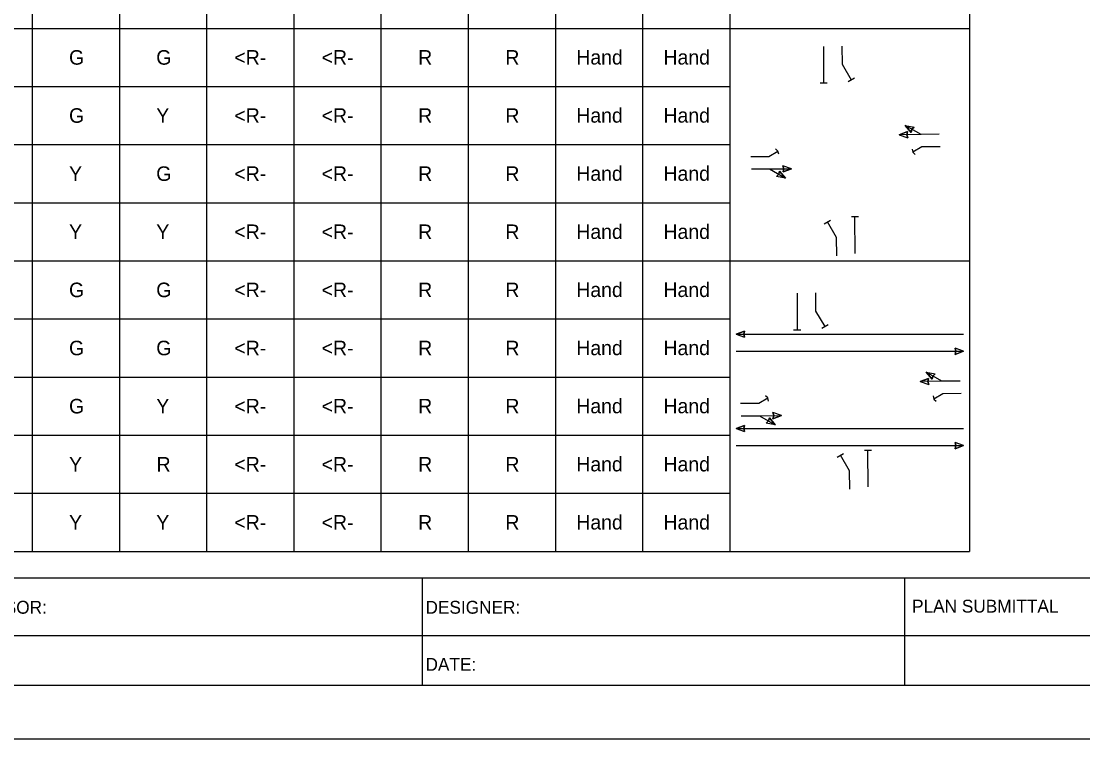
# Model space of a CAD drawing. Extents: x 515543 to 517243, y 660510 to 662861.
# Drawn here: x 515943.9 to 516438.4, y 660510.2 to 660844.6 of the extents above; entities that cross this region are included whole.
import ezdxf

# ---------------------------------------------------------------- set-up
doc = ezdxf.new("R2010")
doc.units = 0
for name, color, linetype in [('ANNO-TXT', 7, 'Continuous'), ('Default', 7, 'Continuous'), ('Level 62', 7, 'Continuous'), ('SHT-BDR', 7, 'Continuous'), ('SHT-BNDRY', 7, 'Continuous')]:
    doc.layers.add(name, color=color, linetype=linetype)

msp = doc.modelspace()

# ---------------------------------------------------------------- linework, layer by layer
at = {"layer": 'Default'}
for p, q in [((515948.98, 661193.38), (515948.98, 660597.54)), ((515989.6, 661193.38), (515989.6, 660597.54)), ((516030.23, 661193.38), (516030.23, 660597.54)), ((516070.85, 661193.38), (516070.85, 660597.54)), ((516111.48, 661193.38), (516111.48, 660597.54)), ((516152.1, 661193.38), (516152.1, 660597.54)), ((516192.73, 661193.38), (516192.73, 660597.54)), ((516233.35, 661193.38), (516233.35, 660597.54)), ((516273.98, 661193.38), (516273.98, 660597.54)), ((516385.67, 661193.38), (516385.67, 660597.54)), ((515695.04, 660841.29), (516385.67, 660841.29)), ((516317.65, 660832.88), (516317.69, 660815.84)), ((516326.16, 660833.02), (516326.25, 660824.55)), ((516326.25, 660824.55), (516330.56, 660817.27)), ((516316, 660815.83), (516319.38, 660815.84)), ((516332.01, 660818.13), (516329.1, 660816.41)), ((515776.29, 660814.21), (516263.79, 660814.21)), ((515776.29, 660814.21), (516273.98, 660814.21)), ((516363.07, 660791.85), (516355.69, 660796)), ((516355.69, 660796), (516358.45, 660792.79)), ((516355.69, 660796), (516359.87, 660795.31)), ((516352.86, 660791.64), (516356.8, 660793.18)), ((516363.07, 660791.85), (516352.86, 660791.64)), ((516352.86, 660791.64), (516356.87, 660790.28)), ((516356.8, 660793.18), (516356.41, 660791.72)), ((516356.41, 660791.72), (516356.87, 660790.28)), ((516358.45, 660792.79), (516358.79, 660794.26)), ((516358.79, 660794.26), (516359.87, 660795.31)), ((516371.53, 660791.94), (516363.07, 660791.85)), ((516371.53, 660791.94), (516363.07, 660791.85)), ((515776.29, 660787.13), (516273.98, 660787.13)), ((515776.29, 660787.13), (516273.98, 660787.13)), ((515948.98, 660787.13), (516273.98, 660787.13)), ((515948.98, 660787.13), (516273.98, 660787.13)), ((516363.5, 660786.02), (516359.27, 660783.52)), ((516371.96, 660786.11), (516363.5, 660786.02)), ((516283.69, 660781.6), (516292.15, 660781.6)), ((516292.15, 660781.6), (516296.41, 660784.06)), ((516296.41, 660784.06), (516295.32, 660785.1)), ((516296.76, 660782.59), (516296.41, 660784.06)), ((516358.9, 660784.98), (516359.27, 660783.52)), ((516359.27, 660783.52), (516360.37, 660782.49)), ((516292.52, 660775.77), (516302.73, 660775.88)), ((516302.73, 660775.88), (516298.74, 660777.27)), ((516299.18, 660775.83), (516298.74, 660777.27)), ((516302.73, 660775.88), (516298.77, 660774.38)), ((516298.77, 660774.38), (516299.18, 660775.83)), ((516284.06, 660775.77), (516292.52, 660775.77)), ((516284.06, 660775.77), (516292.52, 660775.77)), ((516292.52, 660775.77), (516299.85, 660771.54)), ((516296.78, 660773.32), (516295.69, 660772.27)), ((516299.85, 660771.54), (516295.69, 660772.27)), ((516297.13, 660774.78), (516296.78, 660773.32)), ((516299.85, 660771.54), (516297.13, 660774.78)), ((515776.29, 660760.04), (516263.79, 660760.04)), ((515776.29, 660760.04), (516273.98, 660760.04)), ((516317.97, 660750.24), (516320.89, 660751.97)), ((516323.74, 660743.82), (516319.43, 660751.11)), ((516333.98, 660753.41), (516330.59, 660753.4)), ((516332.33, 660736.37), (516332.29, 660753.41)), ((516323.83, 660735.36), (516323.74, 660743.82)), ((515695.04, 660732.96), (516385.67, 660732.96)), ((516305.35, 660717.9), (516305.39, 660700.86)), ((516313.86, 660718.04), (516313.95, 660709.57)), ((516313.95, 660709.57), (516318.26, 660702.29)), ((515776.29, 660705.88), (516263.79, 660705.88)), ((515776.29, 660705.88), (516273.98, 660705.88)), ((516319.72, 660703.15), (516316.8, 660701.43)), ((516276.9, 660698.79), (516280.88, 660700.23)), ((516276.9, 660698.79), (516382.86, 660698.79)), ((516276.9, 660698.79), (516280.88, 660697.34)), ((516280.88, 660700.23), (516280.46, 660698.79)), ((516280.46, 660698.79), (516280.88, 660697.34)), ((516303.7, 660700.86), (516307.09, 660700.86)), ((516382.86, 660690.8), (516378.88, 660692.24)), ((516379.31, 660690.8), (516378.88, 660692.24)), ((516276.9, 660690.8), (516382.86, 660690.8)), ((516382.86, 660690.8), (516378.88, 660689.35)), ((516378.88, 660689.35), (516379.31, 660690.8)), ((515776.29, 660678.79), (516273.98, 660678.79)), ((515776.29, 660678.79), (516273.98, 660678.79)), ((515948.98, 660678.79), (516273.98, 660678.79)), ((515948.98, 660678.79), (516273.98, 660678.79)), ((516362.6, 660676.66), (516366.55, 660678.2)), ((516372.81, 660676.87), (516365.44, 660681.03)), ((516365.44, 660681.03), (516368.19, 660677.81)), ((516365.44, 660681.03), (516369.61, 660680.34)), ((516366.55, 660678.2), (516366.16, 660676.74)), ((516368.19, 660677.81), (516368.53, 660679.28)), ((516368.53, 660679.28), (516369.61, 660680.34)), ((516381.27, 660676.96), (516372.81, 660676.87)), ((516381.27, 660676.96), (516372.81, 660676.87)), ((516372.81, 660676.87), (516362.6, 660676.66)), ((516362.6, 660676.66), (516366.61, 660675.3)), ((516366.16, 660676.74), (516366.61, 660675.3)), ((516287.42, 660666.62), (516291.67, 660669.08)), ((516291.67, 660669.08), (516290.58, 660670.12)), ((516292.03, 660667.61), (516291.67, 660669.08)), ((516368.64, 660670.01), (516369.02, 660668.54)), ((516373.24, 660671.04), (516369.02, 660668.54)), ((516369.02, 660668.54), (516370.12, 660667.51)), ((516381.71, 660671.13), (516373.24, 660671.04)), ((516278.96, 660666.62), (516287.42, 660666.62)), ((516298, 660660.9), (516294, 660662.3)), ((516294.44, 660660.85), (516294, 660662.3)), ((516279.33, 660660.79), (516287.79, 660660.79)), ((516279.33, 660660.79), (516287.79, 660660.79)), ((516287.79, 660660.79), (516298, 660660.9)), ((516287.79, 660660.79), (516295.12, 660656.56)), ((516292.04, 660658.34), (516290.95, 660657.3)), ((516295.12, 660656.56), (516290.95, 660657.3)), ((516292.4, 660659.8), (516292.04, 660658.34)), ((516295.12, 660656.56), (516292.4, 660659.8)), ((516298, 660660.9), (516294.04, 660659.4)), ((516294.04, 660659.4), (516294.44, 660660.85)), ((516276.9, 660654.84), (516280.88, 660656.29)), ((516276.9, 660654.84), (516382.86, 660654.84)), ((516276.9, 660654.84), (516280.88, 660653.4)), ((516280.88, 660656.29), (516280.46, 660654.84)), ((516280.46, 660654.84), (516280.88, 660653.4)), ((515776.29, 660651.71), (516263.79, 660651.71)), ((515776.29, 660651.71), (516273.98, 660651.71)), ((516382.86, 660646.85), (516378.88, 660648.3)), ((516379.31, 660646.85), (516378.88, 660648.3)), ((516276.9, 660646.85), (516382.86, 660646.85)), ((516324.03, 660641.48), (516326.94, 660643.21)), ((516329.79, 660635.06), (516325.48, 660642.34)), ((516340.03, 660644.65), (516336.65, 660644.64)), ((516338.38, 660627.61), (516338.34, 660644.65)), ((516382.86, 660646.85), (516378.88, 660645.41)), ((516378.88, 660645.41), (516379.31, 660646.85)), ((516329.88, 660626.6), (516329.79, 660635.06)), ((515776.29, 660624.63), (516273.98, 660624.63)), ((515776.29, 660624.63), (516263.79, 660624.63)), ((515776.29, 660624.63), (516263.79, 660624.63)), ((515695.04, 660597.54), (516385.67, 660597.54))]:
    msp.add_line(p, q, dxfattribs=at)
for points in [[(516358.45, 660792.79), (516355.69, 660796), (516359.87, 660795.31), (516358.79, 660794.26), (516358.45, 660792.79)], [(516356.8, 660793.18), (516352.86, 660791.64), (516356.87, 660790.28), (516356.41, 660791.72), (516356.8, 660793.18)], [(516298.77, 660774.38), (516302.73, 660775.88), (516298.74, 660777.27), (516299.18, 660775.83), (516298.77, 660774.38)], [(516297.13, 660774.78), (516299.85, 660771.54), (516295.69, 660772.27), (516296.78, 660773.32), (516297.13, 660774.78)], [(516280.88, 660700.23), (516276.9, 660698.79), (516280.88, 660697.34), (516280.46, 660698.79), (516280.88, 660700.23)], [(516378.88, 660689.35), (516382.86, 660690.8), (516378.88, 660692.24), (516379.31, 660690.8), (516378.88, 660689.35)], [(516366.55, 660678.2), (516362.6, 660676.66), (516366.61, 660675.3), (516366.16, 660676.74), (516366.55, 660678.2)], [(516368.19, 660677.81), (516365.44, 660681.03), (516369.61, 660680.34), (516368.53, 660679.28), (516368.19, 660677.81)], [(516294.04, 660659.4), (516298, 660660.9), (516294, 660662.3), (516294.44, 660660.85), (516294.04, 660659.4)], [(516292.4, 660659.8), (516295.12, 660656.56), (516290.95, 660657.3), (516292.04, 660658.34), (516292.4, 660659.8)], [(516280.88, 660656.29), (516276.9, 660654.84), (516280.88, 660653.4), (516280.46, 660654.84), (516280.88, 660656.29)], [(516378.88, 660645.41), (516382.86, 660646.85), (516378.88, 660648.3), (516379.31, 660646.85), (516378.88, 660645.41)]]:
    msp.add_lwpolyline(points, dxfattribs=at)
at = {"layer": 'Level 62'}
msp.add_lwpolyline([(515542.51, 660510.25), (517242.52, 660510.25), (517242.52, 661610.25), (515542.51, 661610.25)], close=True, dxfattribs=at)
at = {"layer": 'SHT-BDR'}
msp.add_lwpolyline([(515667.5, 660585.3), (517167.5, 660585.3), (517167.5, 661535.3), (515667.5, 661535.3)], close=True, dxfattribs=at)
at = {"layer": 'SHT-BNDRY'}
for p, q in [((516130.82, 660535.25), (516130.82, 660585.3)), ((516355.45, 660535.25), (516355.45, 660585.3)), ((515667.5, 660558.3), (516445.64, 660558.3))]:
    msp.add_line(p, q, dxfattribs=at)
msp.add_lwpolyline([(515605.01, 660535.25), (517217.52, 660535.25), (517217.52, 661585.25), (515605.01, 661585.25)], close=True, dxfattribs=at)

# ---------------------------------------------------------------- texts
at = {"layer": 'ANNO-TXT'}
for s, p in [('SUPERVISOR:', (515900.99, 660568.52)), ('DESIGNER:', (516132.21, 660568.52)), ('PLAN SUBMITTAL', (516358.87, 660569.04)), ('DATE:', (516132.21, 660541.92))]:
    msp.add_text(s, height=6, rotation=360, dxfattribs=at).set_placement(p)
at = {"layer": 'Default'}
for s, height, p in [('G', 6.77, (515966.16, 660824.36)), ('G', 6.77, (516006.78, 660824.36)), ('<R-', 6.771, (516043.19, 660824.37)), ('<R-', 6.771, (516043.19, 660824.37)), ('<R-', 6.771, (516083.82, 660824.37)), ('<R-', 6.771, (516083.82, 660824.37)), ('R', 6.77, (516128.81, 660824.37)), ('R', 6.77, (516128.81, 660824.37)), ('R', 6.77, (516169.43, 660824.37)), ('R', 6.77, (516169.43, 660824.37)), ('Hand', 6.771, (516202.46, 660824.42)), ('Hand', 6.771, (516202.46, 660824.42)), ('Hand', 6.771, (516243.08, 660824.42)), ('Hand', 6.771, (516243.08, 660824.42)), ('G', 6.77, (515966.16, 660797.28)), ('Y', 6.77, (516006.81, 660797.28)), ('<R-', 6.771, (516043.19, 660797.28)), ('<R-', 6.771, (516043.19, 660797.28)), ('<R-', 6.771, (516083.82, 660797.28)), ('<R-', 6.771, (516083.82, 660797.28)), ('R', 6.77, (516128.81, 660797.28)), ('R', 6.77, (516128.81, 660797.28)), ('R', 6.77, (516169.43, 660797.28)), ('R', 6.77, (516169.43, 660797.28)), ('Hand', 6.771, (516202.46, 660797.34)), ('Hand', 6.771, (516202.46, 660797.34)), ('Hand', 6.771, (516243.08, 660797.34)), ('Hand', 6.771, (516243.08, 660797.34)), ('Y', 6.77, (515966.18, 660770.2)), ('G', 6.77, (516006.78, 660770.2)), ('<R-', 6.771, (516043.19, 660770.2)), ('<R-', 6.771, (516043.19, 660770.2)), ('<R-', 6.771, (516083.82, 660770.2)), ('<R-', 6.771, (516083.82, 660770.2)), ('R', 6.77, (516128.81, 660770.2)), ('R', 6.77, (516128.81, 660770.2)), ('R', 6.77, (516169.43, 660770.2)), ('R', 6.77, (516169.43, 660770.2)), ('Hand', 6.771, (516202.46, 660770.25)), ('Hand', 6.771, (516243.08, 660770.25)), ('Y', 6.77, (515966.18, 660743.12)), ('Y', 6.77, (516006.81, 660743.12)), ('<R-', 6.771, (516043.19, 660743.12)), ('<R-', 6.771, (516043.19, 660743.12)), ('<R-', 6.771, (516083.82, 660743.12)), ('<R-', 6.771, (516083.82, 660743.12)), ('R', 6.77, (516128.81, 660743.12)), ('R', 6.77, (516128.81, 660743.12)), ('R', 6.77, (516169.43, 660743.12)), ('R', 6.77, (516169.43, 660743.12)), ('Hand', 6.771, (516202.46, 660743.17)), ('Hand', 6.771, (516243.08, 660743.17)), ('G', 6.77, (515966.16, 660716.03)), ('G', 6.77, (516006.78, 660716.03)), ('<R-', 6.771, (516043.19, 660716.03)), ('<R-', 6.771, (516043.19, 660716.03)), ('<R-', 6.771, (516083.82, 660716.03)), ('<R-', 6.771, (516083.82, 660716.03)), ('R', 6.77, (516128.81, 660716.03)), ('R', 6.77, (516128.81, 660716.03)), ('R', 6.77, (516169.43, 660716.03)), ('R', 6.77, (516169.43, 660716.03)), ('Hand', 6.771, (516202.46, 660716.09)), ('Hand', 6.771, (516243.08, 660716.09)), ('Hand', 6.771, (516243.08, 660716.09)), ('G', 6.77, (515966.16, 660688.95)), ('G', 6.77, (516006.78, 660688.95)), ('<R-', 6.771, (516043.19, 660688.95)), ('<R-', 6.771, (516043.19, 660688.95)), ('<R-', 6.771, (516083.82, 660688.95)), ('<R-', 6.771, (516083.82, 660688.95)), ('R', 6.77, (516128.81, 660688.95)), ('R', 6.77, (516128.81, 660688.95)), ('R', 6.77, (516169.43, 660688.95)), ('R', 6.77, (516169.43, 660688.95)), ('Hand', 6.771, (516202.46, 660689)), ('Hand', 6.771, (516243.08, 660689)), ('Hand', 6.771, (516243.08, 660689)), ('G', 6.77, (515966.16, 660661.86)), ('Y', 6.77, (516006.81, 660661.87)), ('<R-', 6.771, (516043.19, 660661.87)), ('<R-', 6.771, (516043.19, 660661.87)), ('<R-', 6.771, (516083.82, 660661.87)), ('<R-', 6.771, (516083.82, 660661.87)), ('R', 6.77, (516128.81, 660661.87)), ('R', 6.77, (516128.81, 660661.87)), ('R', 6.77, (516169.43, 660661.87)), ('R', 6.77, (516169.43, 660661.87)), ('Hand', 6.771, (516202.46, 660661.92)), ('Hand', 6.771, (516243.08, 660661.92)), ('Y', 6.77, (515966.18, 660634.78)), ('R', 6.77, (516006.93, 660634.78)), ('R', 6.77, (516006.93, 660634.78)), ('<R-', 6.771, (516043.19, 660634.78)), ('<R-', 6.771, (516043.19, 660634.78)), ('<R-', 6.771, (516083.82, 660634.78)), ('<R-', 6.771, (516083.82, 660634.78)), ('R', 6.77, (516128.81, 660634.78)), ('R', 6.77, (516128.81, 660634.78)), ('R', 6.77, (516169.43, 660634.78)), ('R', 6.77, (516169.43, 660634.78)), ('Hand', 6.771, (516202.46, 660634.84)), ('Hand', 6.771, (516243.08, 660634.84)), ('Y', 6.77, (515966.18, 660607.7)), ('Y', 6.77, (516006.81, 660607.7)), ('<R-', 6.771, (516043.19, 660607.7)), ('<R-', 6.771, (516043.19, 660607.7)), ('<R-', 6.771, (516083.82, 660607.7)), ('<R-', 6.771, (516083.82, 660607.7)), ('R', 6.77, (516128.81, 660607.7)), ('R', 6.77, (516128.81, 660607.7)), ('R', 6.77, (516169.43, 660607.7)), ('R', 6.77, (516169.43, 660607.7)), ('Hand', 6.771, (516202.46, 660607.75)), ('Hand', 6.771, (516243.08, 660607.75))]:
    msp.add_text(s, height=height, dxfattribs=at).set_placement(p)

doc.saveas('drawing.dxf')
